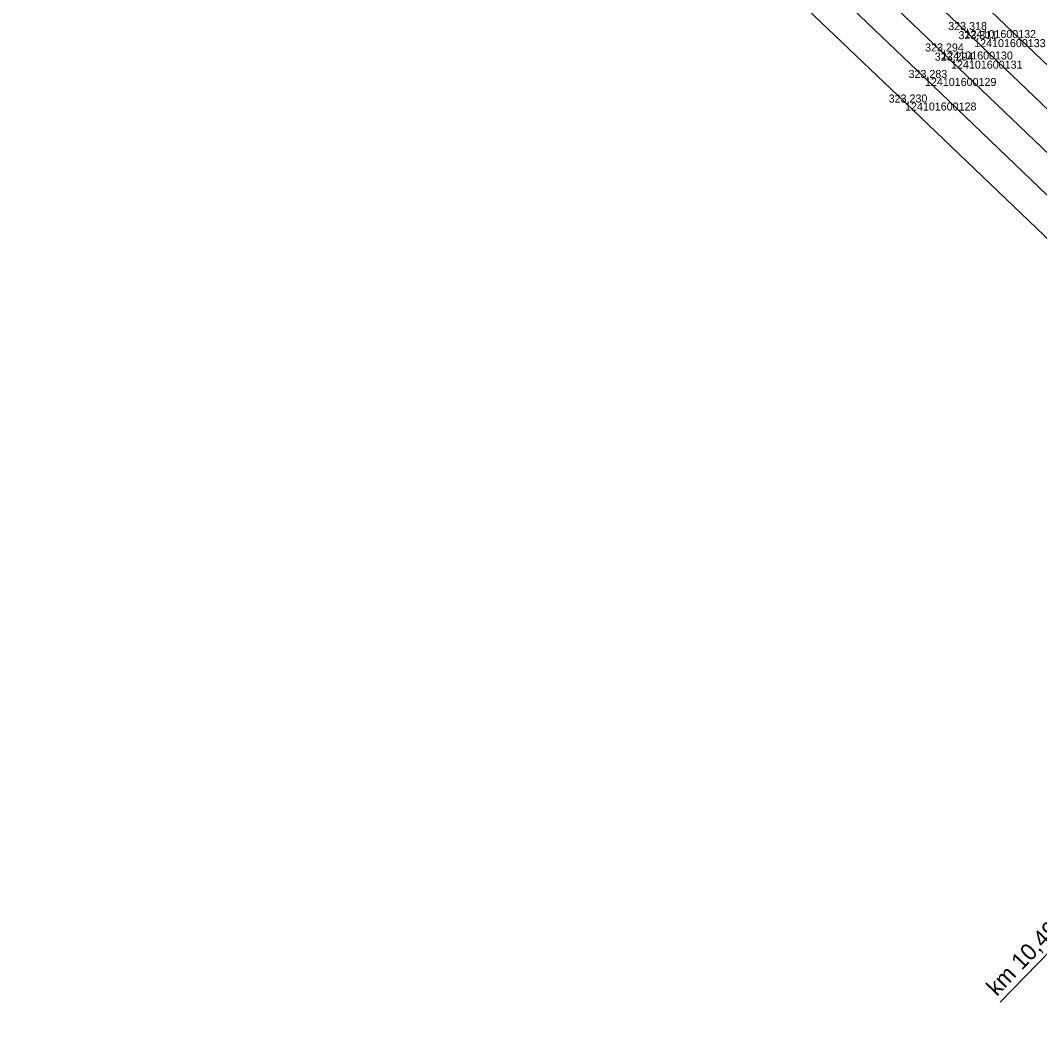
# Model space of a CAD drawing. Extents: x -616949 to -607976, y -1164436 to -1159224.
# Drawn here: x -616496.4 to -616343.7, y -1159722.9 to -1159570.1 of the extents above; entities that cross this region are included whole.
import ezdxf

# ---------------------------------------------------------------- set-up
doc = ezdxf.new("R2010")
doc.units = 0
for name, color, linetype in [('Vrstva 1', 7, 'Continuous'), ('Vrstva 3', 7, 'Continuous'), ('Vrstva 4', 7, 'Continuous'), ('Vrstva 60', 7, 'Continuous'), ('Vrstva 61', 7, 'Continuous')]:
    doc.layers.add(name, color=color, linetype=linetype)

msp = doc.modelspace()

# ---------------------------------------------------------------- linework, layer by layer
at = {"layer": 'Vrstva 1'}
for points in [[(-616239.15, -1159697.79), (-616239.8, -1159697.28), (-616244.33, -1159693.92), (-616259.78, -1159681.25), (-616268.13, -1159673.95), (-616278.58, -1159664.07), (-616288.41, -1159654.65), (-616299.9, -1159643.65), (-616322.63, -1159621.82), (-616340.65, -1159604.54), (-616363.83, -1159582.4), (-616382.82, -1159564.27), (-616397.71, -1159550.06), (-616401.16, -1159546.79), (-616418.73, -1159530.01), (-616439.27, -1159510.4), (-616452.37, -1159497.82), (-616461.42, -1159488.93), (-616469.22, -1159481.07), (-616478.64, -1159471.37), (-616490.77, -1159457.29), (-616495.92, -1159451.32), (-616496.45, -1159450.7)], [(-616196.14, -1159722.89), (-616196.73, -1159722.32), (-616202.46, -1159716.91), (-616215.79, -1159704.32), (-616232.19, -1159688.78), (-616245.9, -1159675.68), (-616250.85, -1159670.95), (-616252.01, -1159669.85), (-616262.33, -1159660.01), (-616274.66, -1159648.21), (-616291.39, -1159632.22), (-616312.18, -1159612.35), (-616313.6, -1159610.97), (-616321.94, -1159603.01), (-616323.38, -1159601.63), (-616330.7, -1159594.64), (-616332.15, -1159593.27), (-616353.46, -1159572.9), (-616354.89, -1159571.54), (-616372.69, -1159554.54)], [(-616335.34, -1159596.8), (-616356.93, -1159576.13), (-616358.37, -1159574.75), (-616375.97, -1159557.93)], [(-616218.05, -1159715.21), (-616218.66, -1159714.63), (-616224.36, -1159709.19), (-616237.66, -1159696.51), (-616252.73, -1159682.15), (-616263.69, -1159671.68), (-616264.9, -1159670.55), (-616281.06, -1159655.11), (-616297.26, -1159639.59), (-616319.41, -1159618.4), (-616337.57, -1159601.02), (-616360.84, -1159578.72), (-616379.28, -1159561.06)], [(-616196.14, -1159722.89), (-616196.73, -1159722.32), (-616202.46, -1159716.91), (-616214.6, -1159702.79), (-616223.47, -1159692.48), (-616229.46, -1159685.74), (-616241.59, -1159673.27), (-616259.02, -1159656.6), (-616271.36, -1159644.82), (-616287.75, -1159629.14), (-616308.99, -1159608.84), (-616310.74, -1159607.16), (-616318.53, -1159599.72), (-616320.21, -1159598.1), (-616327.35, -1159591.27), (-616329.08, -1159589.6), (-616351, -1159568.64)]]:
    msp.add_lwpolyline(points, dxfattribs=at)
at = {"layer": 'Vrstva 3'}
msp.add_line((-616288.41, -1159654.65), (-616349.59, -1159717.25), dxfattribs=at)
at = {"layer": 'Vrstva 4'}
for p, q in [((-616353.46, -1159572.9), (-616354.89, -1159571.54)), ((-616356.93, -1159576.13), (-616358.37, -1159574.75))]:
    msp.add_line(p, q, dxfattribs=at)
at = {"layer": 'Vrstva 60'}
for p, q in [((-616354.89, -1159571.54), (-616354.89, -1159571.54)), ((-616353.46, -1159572.9), (-616353.46, -1159572.9)), ((-616358.37, -1159574.75), (-616358.37, -1159574.75)), ((-616356.93, -1159576.13), (-616356.93, -1159576.13)), ((-616360.84, -1159578.72), (-616360.84, -1159578.72)), ((-616363.83, -1159582.4), (-616363.83, -1159582.4))]:
    msp.add_line(p, q, dxfattribs=at)

# ---------------------------------------------------------------- texts
at = {"layer": 'Vrstva 3'}
msp.add_text('km 10,497', height=2.5, rotation=46.1695, dxfattribs=at).set_placement((-616350.07, -1159716.49))
at = {"layer": 'Vrstva 60'}
for s, p in [('124101600132', (-616354.89, -1159572.74)), ('124101600133', (-616353.46, -1159574.1)), ('124101600130', (-616358.37, -1159575.95)), ('124101600131', (-616356.93, -1159577.33)), ('124101600129', (-616360.84, -1159579.92)), ('124101600128', (-616363.83, -1159583.6))]:
    msp.add_text(s, height=1.2, dxfattribs=at).set_placement(p)
at = {"layer": 'Vrstva 61'}
for s, p in [('323.318', (-616357.35, -1159571.54)), ('323.311', (-616355.82, -1159572.9)), ('323.294', (-616360.82, -1159574.75)), ('323.294', (-616359.38, -1159576.13)), ('323.283', (-616363.3, -1159578.72)), ('323.230', (-616366.28, -1159582.4))]:
    msp.add_text(s, height=1.2, dxfattribs=at).set_placement(p)

doc.saveas('drawing.dxf')
